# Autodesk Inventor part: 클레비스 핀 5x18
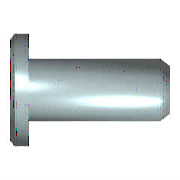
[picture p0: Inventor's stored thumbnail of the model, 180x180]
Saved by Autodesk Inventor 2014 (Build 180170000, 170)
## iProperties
IsCustomPart: 0
Created: 2012-02
Part Number: 클레비스 핀 5x18
Material: 강철
Description: 머리가 있는 클레비스 핀
Document SubType Name: Modeling
Standard: ISO 2341
Designer: mduedu
Standard Revision: Second edition 1986-11-01
Standards Organization: ISO
Language: ko-KR
Size Designation: A - 5 x 18
Categories: <MemberInstance><Categories><Category DisplayName="조임쇠" InternalName="e4da775c-781d-43d5-af7c-5136215cf5a6" Mnemonic="FSTN"><Category DisplayName="핀" InternalNa
Density: 7.85 g/cm^3
Mass: 3.15865 g
Surface Area: 4.03301 cm^2
Volume: 0.402376 cm^3
Appearance: 노란색
Author: mduedu
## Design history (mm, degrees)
sketch "스케치1"
  geometry: L1 (-1.6, 0)-(-1.6, 4); L2 (-1.6, 4)-(0, 4); L3 (0, 4)-(0, 2.5); L4 (0, 2.5)-(18, 2.5); L5 (18, 2.5)-(18, 0); L6 (-1.6, 0)-(18, 0); L7 (-4, 0)-(17, 0) reference; L8 (0, -0.5)-(0, 3) reference
  constraints: 12 end point, 3 parallel, 2 collinear, 2 perpendicular, 1 vertical
  dimensions: "d0" = 1.6 distance of L1.end L2.end (= KOH); "d1" = 18 distance of L3.end L4.end (= NLG); "d2" = 5 diameter of L4 L6 (= NND); "d3" = 8 diameter of L2 L6 (= KOD)
revolve "본체" sketch "스케치1" stored, may be unused: angle "d5" = 90 deg
node "작업 평면1"
sketch "스케치2"
  geometry: C1 r 2.5 at (0, 0) reference; C2 r 1.95 at (0, 0); 1 further point
  constraints: 1 centre point, 1 coincident
  dimensions: "d16" = 3.9 diameter of C2
extrude "돌출1" cut sketch "스케치2" distance "d17" = 0.6; taper "d18" = 0 deg
body "Solid1"
chamfer "모따기1" distance "d7" = 2 (= PHH1); stored, may be unused: angle "d8" = 30 deg (= FAWI1), second distance "d12" = 2 (= PHH1)
chamfer "모따기2" distance "d4" = 1 (= PHH2); stored, may be unused: angle "d6" = 45 deg (= FAWI2), second distance "d13" = 1 (= PHH2)
other parameters: "NLG" = 18 [user parameter; used in 1 equation term], "KOH" = 1.6 [user parameter; used in 1 equation term], "KOD" = 8 [user parameter; used in 1 equation term], "NND" = 5 [user parameter; used in 1 equation term], "FAWI1" = 30 deg [user parameter; used in 1 equation term], "FAWI2" = 45 deg [user parameter; used in 1 equation term], "PHH2" = 1 [user parameter; used in 2 equation terms], "PHH1" = 2 [user parameter; used in 2 equation terms], "d9" = 0, "d10" = 0, "d14" = 0, "d15" = 13
